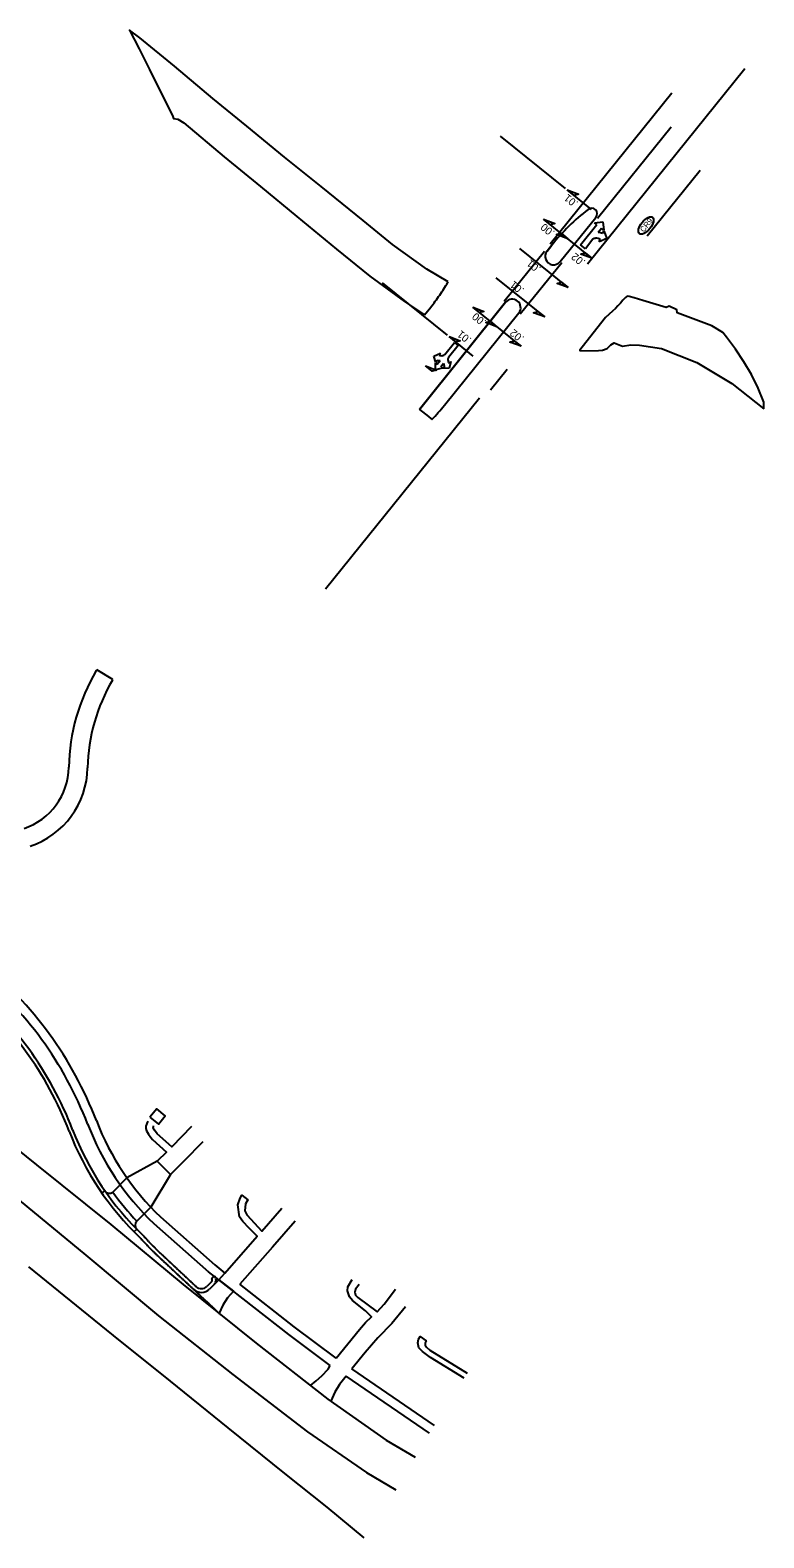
# Model space of a CAD drawing. Extents: x 1487693 to 1489338, y 497936 to 499734.
# Drawn here: x 1488948 to 1489338, y 498934 to 499734 of the extents above; entities that cross this region are included whole.
import ezdxf

# ---------------------------------------------------------------- set-up
doc = ezdxf.new("R2010")
doc.units = 0
for name, color, linetype in [('Default', 7, 'Continuous'), ('Exist Railroads Standard Gauge', 7, 'Continuous'), ('Exist Roads EOP', 7, 'Continuous'), ('Exist Roads EOP Other', 7, 'Continuous'), ('Prop Conc 2ft 6in Curb and Gutter', 7, 'Continuous'), ('Prop Conc 4in Sidewalk', 7, 'Continuous'), ('Prop Conc Driveway', 7, 'Continuous'), ('Prop EOT', 7, 'Continuous'), ('Prop Paved Shoulder', 7, 'Continuous')]:
    doc.layers.add(name, color=color, linetype=linetype)

msp = doc.modelspace()

# ---------------------------------------------------------------- linework, layer by layer
at = {"layer": 'Default'}
for p, q in [((1489244.14, 499610.15), (1489327.8, 499713.89)), ((1489224.38, 499620.7), (1489289.04, 499700.88)), ((1489232.52, 499650.11), (1489197.98, 499677.97)), ((1489288.57, 499682.77), (1489249.4, 499634.2)), ((1489275.86, 499625.03), (1489304, 499659.93)), ((1489246.24, 499639.04), (1489233.4, 499649.4)), ((1489246.53, 499613.12), (1489220.84, 499633.83)), ((1489229.66, 499611.31), (1489248.62, 499634.83)), ((1489229.66, 499611.31), (1489248.62, 499634.83)), ((1489240.45, 499620.27), (1489249.11, 499631.01)), ((1489247.95, 499631.95), (1489252.35, 499632.39)), ((1489249.11, 499631.01), (1489247.95, 499631.95)), ((1489251.68, 499628.94), (1489249.89, 499626.72)), ((1489252.85, 499628), (1489251.68, 499628.94)), ((1489252.35, 499632.39), (1489252.85, 499628)), ((1489247.07, 499623.22), (1489243.02, 499618.2)), ((1489254.43, 499623.51), (1489250.31, 499621.89)), ((1489250.31, 499621.89), (1489250.87, 499623.24)), ((1489252.22, 499626.26), (1489252.82, 499627.64)), ((1489252.82, 499627.64), (1489254.43, 499623.51)), ((1489199.9, 499590.34), (1489221.25, 499616.81)), ((1489233.98, 499597.55), (1489208.29, 499618.27)), ((1489222.65, 499616.96), (1489225.16, 499620.07)), ((1489225.16, 499620.07), (1489222.65, 499616.96)), ((1489243.02, 499618.2), (1489240.45, 499620.27)), ((1489230.44, 499610.68), (1489208.46, 499583.44)), ((1489169.75, 499572.27), (1489135.21, 499600.12)), ((1489221.42, 499581.98), (1489195.73, 499602.7)), ((1489154.86, 499532.89), (1489200.68, 499589.72)), ((1489200.68, 499589.72), (1489154.86, 499532.89)), ((1489168.14, 499535.03), (1489207.69, 499584.07)), ((1489168.14, 499535.03), (1489207.69, 499584.07)), ((1489208.87, 499566.41), (1489183.18, 499587.13)), ((1489168.4, 499561.93), (1489173.59, 499568.33)), ((1489175.46, 499566.81), (1489170.25, 499560.37)), ((1489183.47, 499561.2), (1489170.62, 499571.56)), ((1489173.59, 499568.33), (1489175.46, 499566.81)), ((1489162.61, 499561.16), (1489166, 499562.8)), ((1489163.53, 499557.84), (1489162.61, 499561.16)), ((1489163.45, 499553.83), (1489163.5, 499557.49)), ((1489163.5, 499557.49), (1489164.29, 499556.85)), ((1489164.09, 499559.02), (1489163.53, 499557.84)), ((1489164.29, 499556.85), (1489165.88, 499558.82)), ((1489166, 499562.8), (1489165.44, 499561.62)), ((1489167.73, 499557.26), (1489166.17, 499555.33)), ((1489170.6, 499557.45), (1489171.64, 499558.24)), ((1489171.64, 499558.24), (1489170.7, 499554.6)), ((1489166.95, 499554.69), (1489163.45, 499553.83)), ((1489166.17, 499555.33), (1489166.95, 499554.69)), ((1489167.29, 499554.79), (1489168.33, 499555.58)), ((1489170.7, 499554.6), (1489167.29, 499554.79)), ((1489201.46, 499554.04), (1489192.67, 499543.14)), ((1489105.05, 499437.68), (1489186.71, 499538.94)), ((1489159.62, 499529.05), (1489161.18, 499527.79)), ((1489161.18, 499527.79), (1489161.56, 499527.49))]:
    msp.add_line(p, q, dxfattribs=at)
for points in [[(1489170.07, 499600.67), (1489158.75, 499607.4), (1489140.66, 499620.46), (1489125.03, 499633.21), (1489102.63, 499651.13), (1489083.17, 499666.86), (1489063.28, 499683.21), (1489045.07, 499697.98), (1489024.72, 499715.05), (1489006.27, 499730.11), (1489000.95, 499734.21), (1489005.92, 499724.24)], [(1489005.92, 499724.24), (1489011.46, 499713.24), (1489016.16, 499703.9), (1489023.69, 499688.94)], [(1489023.69, 499688.94), (1489024.3, 499687.23), (1489026.5, 499686.99), (1489029.65, 499684.95), (1489051.14, 499666.9), (1489070.45, 499651.25), (1489089.7, 499635.25), (1489110.82, 499618.01), (1489128.51, 499603.56), (1489146.94, 499590.2), (1489157.49, 499583.15)], [(1489157.49, 499583.15), (1489158.35, 499584.03), (1489160.27, 499586.34), (1489161.54, 499587.88), (1489162.14, 499588.68), (1489162.75, 499589.48), (1489163.32, 499590.3), (1489163.91, 499591.11), (1489164.51, 499591.91), (1489165.09, 499592.73), (1489165.67, 499593.54), (1489166.23, 499594.38), (1489166.77, 499595.22), (1489167.31, 499596.07), (1489167.85, 499596.92), (1489168.98, 499598.58), (1489169.52, 499599.43), (1489170.07, 499600.67)], [(1489266.26, 499592.78), (1489266.26, 499592.78), (1489265.22, 499592.91), (1489264.42, 499592.27), (1489263.71, 499591.56), (1489263.01, 499590.84), (1489261.68, 499589.34), (1489260.34, 499587.85), (1489258.95, 499586.4), (1489257.52, 499584.98), (1489253.73, 499581.62), (1489253.72, 499581.62), (1489241.29, 499565.96), (1489240.14, 499564.33), (1489240.17, 499564.01)], [(1489316.01, 499573.61), (1489310.3, 499577.17), (1489291.78, 499584.19), (1489291.69, 499585.76), (1489287.56, 499587.6), (1489285.94, 499587.02), (1489273.63, 499590.72), (1489269.03, 499592.11), (1489266.26, 499592.78)], [(1489337.85, 499533.16), (1489337.76, 499536.7), (1489334.74, 499544.15), (1489331.25, 499551.32), (1489327.17, 499558.17), (1489322.71, 499564.76), (1489318.01, 499571.17), (1489316.01, 499573.61)], [(1489250, 499564.09), (1489252.14, 499564.24), (1489254.62, 499565.28), (1489255.42, 499566.15), (1489256.62, 499567.2), (1489258.31, 499568.22), (1489262.77, 499566.37), (1489267.18, 499567.1)], [(1489267.18, 499567.1), (1489271.81, 499567.03), (1489283.45, 499565.21), (1489302.26, 499557.74), (1489320.91, 499546.7), (1489337.85, 499533.16)], [(1489240.17, 499564.01), (1489250, 499564.09)], [(1489154.86, 499532.89), (1489154.96, 499532.8), (1489156.52, 499531.55), (1489159.62, 499529.05)]]:
    msp.add_lwpolyline(points, dxfattribs=at)
for points in [[(1489233.4, 499649.4), (1489239.33, 499647.19), (1489237, 499646.5)], [(1489220.84, 499633.83), (1489226.77, 499631.62), (1489224.44, 499630.93)], [(1489233.69, 499623.48), (1489227.76, 499625.69), (1489230.09, 499626.38)], [(1489246.53, 499613.12), (1489240.61, 499615.33), (1489242.93, 499616.02)], [(1489233.98, 499597.55), (1489228.05, 499599.76), (1489230.38, 499600.45)], [(1489183.18, 499587.13), (1489189.11, 499584.92), (1489186.78, 499584.23)], [(1489221.42, 499581.98), (1489215.5, 499584.19), (1489217.82, 499584.89)], [(1489196.02, 499576.77), (1489190.1, 499578.98), (1489192.42, 499579.67)], [(1489170.62, 499571.56), (1489176.55, 499569.35), (1489174.22, 499568.66)], [(1489208.87, 499566.41), (1489202.94, 499568.62), (1489205.27, 499569.32)], [(1489158.07, 499555.99), (1489164, 499553.78), (1489161.67, 499553.09)]]:
    msp.add_lwpolyline(points, close=True, dxfattribs=at)
for centre, radius, start, end in [((1489317.79, 499545.37), 119, 128.05665, 141.11565), ((1489317.79, 499545.37), 119, 128.05665, 141.11565), ((1489246.29, 499636.71), 3, 321.11565, 128.05665), ((1489246.29, 499636.71), 3, 321.11565, 128.05665), ((1489248.57, 499621.19), 2.52, 90.18879, 126.50079), ((1489248.85, 499619.29), 4.43, 62.82532, 93.67888), ((1489250.18, 499622.31), 4.43, 62.70651, 93.58511), ((1489226.15, 499614.14), 4.5, 141.11565, 321.11565), ((1489226.15, 499614.14), 4.5, 141.11565, 321.11565), ((1489204.18, 499586.89), 4.5, 321.11565, 141.11565), ((1489204.18, 499586.89), 4.5, 321.11565, 141.11565), ((1489067.72, 499616.01), 129, 316.66965, 321.11565)]:
    msp.add_arc(centre, radius, start, end, dxfattribs=at)
msp.add_ellipse((1489275.24, 499630.49), major_axis=(3.52, 4.36), ratio=0.462467, dxfattribs=at)
for centre, major_axis, start_param, end_param in [((1489166.07, 499562.46), (-2.52, -3.1), 0.196592, 0.735719), ((1489167.4, 499565.08), (-2.52, -3.1), 0.203036, 0.742869), ((1489167.45, 499563.53), (-1.43, -1.77), 0.681955, 1.288737), ((1489171.27, 499558.24), (-2.52, -3.1), 5.554392, 6.091543), ((1489172.03, 499559.82), (-1.43, -1.77), 5.025308, 5.60123), ((1489173.56, 499560.09), (-2.52, -3.1), 5.540317, 6.085081)]:
    msp.add_ellipse(centre, major_axis=major_axis, ratio=0.8, start_param=start_param, end_param=end_param, dxfattribs=at)
at = {"layer": 'Exist Railroads Standard Gauge'}
msp.add_lwpolyline([(1489125.56, 498933.79), (1489105.79, 498950), (1489083.46, 498967.96), (1489053.28, 498992.22), (1489018.86, 499019.95), (1488995.28, 499038.96), (1488972.75, 499057.15), (1488947.35, 499077.62)], dxfattribs=at)
at = {"layer": 'Exist Roads EOP'}
for points in [[(1488820.51, 499188.47), (1488839.08, 499189.45), (1488852.47, 499187.96), (1488871.27, 499182.3), (1488872.89, 499182.88), (1488877.01, 499181.04), (1488877.11, 499179.47), (1488895.62, 499172.45), (1488918.37, 499158.28), (1488951.48, 499131.73), (1488990.9, 499100.07), (1489029.29, 499068.35), (1489068.11, 499037.11), (1489106.28, 499007.35), (1489137.25, 498985.73), (1489152.63, 498976.62)], [(1488852.51, 499162.38), (1488857.14, 499162.31), (1488868.78, 499160.49), (1488887.58, 499153.02), (1488906.23, 499141.98), (1488939.26, 499115.6), (1488977.74, 499083.85), (1489016.26, 499051.68), (1489055.69, 499020.57), (1489095.36, 498990.11), (1489126.76, 498968.54), (1489142.29, 498959.28)]]:
    msp.add_lwpolyline(points, dxfattribs=at)
at = {"layer": 'Exist Roads EOP Other'}
for p, q in [((1489162.83, 498993.48), (1489118.92, 499023.49)), ((1489160.2, 498989.42), (1489115.9, 499019.67))]:
    msp.add_line(p, q, dxfattribs=at)
msp.add_lwpolyline([(1489011.73, 499157.04), (1489016.2, 499153.4), (1489019.84, 499157.87), (1489015.37, 499161.51)], close=True, dxfattribs=at)
for points in [[(1489010.64, 499155.03), (1489010.03, 499153.76), (1489009.6, 499152.43), (1489009.54, 499151.19), (1489009.91, 499149.95), (1489010.9, 499148.11), (1489012.2, 499146.31), (1489013.14, 499145.21), (1489020.5, 499138.63), (1489015.64, 499133.75)], [(1489033.88, 499152.24), (1489023.35, 499141.34), (1489015.58, 499148.35), (1489014.06, 499150.17), (1489013.47, 499151.42), (1489013.56, 499152.09), (1489013.68, 499152.47)], [(1489022.63, 499126.72), (1489029.99, 499134.03), (1489039.99, 499144.23)], [(1489051.56, 499074.32), (1489068.75, 499093.96), (1489064.42, 499098.24), (1489061.03, 499101.7), (1489059.3, 499104.2), (1489058.33, 499110.63), (1489059.61, 499114.21), (1489060.57, 499115.78), (1489063.69, 499113.31), (1489062.48, 499111.17), (1489062.22, 499107.42), (1489063.14, 499105.32), (1489071.13, 499096.65), (1489081.87, 499108.9)], [(1489088.81, 499101.94), (1489076.82, 499088.19), (1489059.44, 499068.48)], [(1489107.54, 499025.35), (1489085.54, 499041.81), (1489048.37, 499070.79)], [(1489110.68, 499029.19), (1489088.27, 499045.74), (1489059.44, 499068.48)], [(1489110.68, 499029.19), (1489123.04, 499044.47), (1489126.27, 499048.2), (1489129.43, 499051.07), (1489126.21, 499054.36), (1489119.29, 499059.75), (1489117.78, 499061.68), (1489116.73, 499064.85), (1489116.8, 499067.06), (1489119.17, 499070.89)], [(1489122.78, 499068.28), (1489120.9, 499065.79), (1489120.51, 499064.19), (1489120.96, 499062.67), (1489122.15, 499061.31), (1489132.4, 499053.85), (1489136.17, 499057.9), (1489142.24, 499065.86)], [(1489147.5, 499056.46), (1489140.18, 499047.54), (1489132.86, 499040.02), (1489126.03, 499032.2), (1489118.92, 499023.49)], [(1489178.68, 499018.65), (1489160.79, 499029.54), (1489156.59, 499032.64), (1489154.62, 499034.62), (1489153.98, 499037.34), (1489154.46, 499039.28), (1489155.28, 499040.73), (1489158.49, 499038.41), (1489158.01, 499037.27), (1489158, 499036.04), (1489158.62, 499035.01), (1489160.47, 499033.46), (1489180.16, 499021.19)], [(1489097.06, 499014.63), (1489100.07, 499017.16), (1489103.11, 499019.85), (1489106.34, 499023.42), (1489107.54, 499025.35)], [(1489115.9, 499019.67), (1489112.46, 499015.27), (1489109.88, 499011.21), (1489107.86, 499006.36)]]:
    msp.add_lwpolyline(points, dxfattribs=at)
at = {"layer": 'Prop Conc 2ft 6in Curb and Gutter'}
for p, q in [((1489044.52, 499069.81), (1489041.95, 499067.29)), ((1489044.43, 499071.32), (1489045.65, 499072.9))]:
    msp.add_line(p, q, dxfattribs=at)
for centre, radius, start, end in [((1488796.55, 499083.6), 186.5, 21.00993, 51.11565), ((1489113.94, 499205.5), 153.5, 201.00993, 226.34297), ((1489043.82, 499070.53), 1, 314.53001, 52.25672), ((1489039.05, 499070.24), 4.14, 226.91206, 314.53)]:
    msp.add_arc(centre, radius, start, end, dxfattribs=at)
msp.add_spline([(1489007.98, 499094.44), (1489008.47, 499093.9), (1489008.96, 499093.35), (1489009.46, 499092.81), (1489009.96, 499092.27), (1489010.46, 499091.73), (1489010.97, 499091.2), (1489011.47, 499090.67), (1489011.99, 499090.14), (1489012.5, 499089.61), (1489013.01, 499089.08), (1489013.53, 499088.56), (1489014.06, 499088.04), (1489014.58, 499087.52), (1489015.11, 499087), (1489015.64, 499086.49), (1489016.17, 499085.98), (1489016.71, 499085.46), (1489017.3, 499084.91), (1489017.9, 499084.35), (1489018.49, 499083.8), (1489019.08, 499083.24), (1489019.68, 499082.69), (1489020.27, 499082.13), (1489020.86, 499081.57), (1489021.46, 499081.02), (1489022.05, 499080.46), (1489022.64, 499079.91), (1489023.24, 499079.35), (1489023.83, 499078.8), (1489024.43, 499078.24), (1489025.02, 499077.69), (1489025.61, 499077.13), (1489026.21, 499076.58), (1489026.8, 499076.02), (1489027.39, 499075.47), (1489027.99, 499074.91), (1489028.58, 499074.36), (1489029.17, 499073.8), (1489029.77, 499073.25), (1489030.36, 499072.69), (1489030.96, 499072.14), (1489031.55, 499071.58), (1489032.14, 499071.02), (1489032.74, 499070.47), (1489033.33, 499069.91), (1489033.92, 499069.36), (1489034.52, 499068.8), (1489035.11, 499068.25), (1489035.7, 499067.69), (1489036.22, 499067.21)], degree=3, dxfattribs=at)
at = {"layer": 'Prop Conc 4in Sidewalk'}
for p, q in [((1488983.22, 499394.23), (1488983.44, 499394.61)), ((1488992.05, 499389.52), (1488983.44, 499394.61)), ((1488991.83, 499389.14), (1488992.05, 499389.52)), ((1489013.84, 499100.59), (1489042.81, 499075.1)), ((1489017.3, 499104.21), (1489046.26, 499078.72)), ((1489046.26, 499078.72), (1489051.56, 499074.32)), ((1489048.37, 499070.79), (1489042.81, 499075.1)), ((1489048.37, 499070.79), (1489051.56, 499074.32))]:
    msp.add_line(p, q, dxfattribs=at)
for centre, radius, start, end in [((1489073.61, 499340.81), 105, 149.4145, 178.88465), ((1489073.61, 499340.81), 95, 149.4145, 178.88465), ((1488933.64, 499343.53), 35, 288.72221, 358.88465), ((1488933.64, 499343.53), 45, 288.72221, 358.88465), ((1488796.55, 499083.6), 200, 21.00993, 51.11565), ((1488796.55, 499083.6), 195, 21.00993, 51.11565), ((1489113.94, 499205.5), 145, 201.00993, 226.34297), ((1489113.94, 499205.5), 140, 201.00993, 226.34297)]:
    msp.add_arc(centre, radius, start, end, dxfattribs=at)
at = {"layer": 'Prop Conc Driveway'}
for p, q in [((1489015.64, 499133.75), (1488999.51, 499124.84)), ((1489022.63, 499126.72), (1489015.64, 499133.75)), ((1488999.51, 499124.84), (1488991.97, 499117.34)), ((1489022.63, 499126.72), (1489012.24, 499109.29)), ((1488986.16, 499116.84), (1488987.78, 499118.01)), ((1489012.24, 499109.29), (1489004.79, 499101.89)), ((1489003.23, 499096.27), (1489004.68, 499097.64))]:
    msp.add_line(p, q, dxfattribs=at)
for centre, radius, start, end in [((1488990.21, 499119.77), 3, 215.94114, 305.8734), ((1489113.34, 499204.99), 149.71, 215.83468, 223.52528), ((1489006.85, 499099.71), 3, 133.49719, 223.47069)]:
    msp.add_arc(centre, radius, start, end, dxfattribs=at)
at = {"layer": 'Prop EOT'}
for p, q in [((1489048.37, 499070.79), (1489043.36, 499065.86)), ((1489048.37, 499070.79), (1489056.05, 499064.71)), ((1489052.88, 499061.14), (1489050.53, 499057.32)), ((1489056.05, 499064.71), (1489052.88, 499061.14)), ((1489050.53, 499057.32), (1489048.41, 499053.08))]:
    msp.add_line(p, q, dxfattribs=at)
for centre, radius, start, end in [((1488796.55, 499083.6), 184.5, 21.00993, 51.11565), ((1489113.94, 499205.5), 155.5, 201.00993, 226.34297), ((1489039.05, 499070.24), 6.14, 226.91206, 314.53)]:
    msp.add_arc(centre, radius, start, end, dxfattribs=at)
msp.add_spline([(1489006.6, 499093), (1489007.09, 499092.44), (1489007.59, 499091.89), (1489008.1, 499091.34), (1489008.61, 499090.8), (1489009.12, 499090.26), (1489009.63, 499089.71), (1489010.14, 499089.17), (1489010.66, 499088.64), (1489011.18, 499088.1), (1489011.7, 499087.57), (1489012.23, 499087.04), (1489012.76, 499086.51), (1489013.29, 499085.99), (1489013.83, 499085.47), (1489014.36, 499084.95), (1489014.9, 499084.43), (1489015.45, 499083.91), (1489016.04, 499083.35), (1489016.64, 499082.8), (1489017.23, 499082.24), (1489017.82, 499081.69), (1489018.42, 499081.13), (1489019.01, 499080.58), (1489019.6, 499080.02), (1489020.2, 499079.47), (1489020.79, 499078.91), (1489021.38, 499078.36), (1489021.98, 499077.8), (1489022.57, 499077.24), (1489023.17, 499076.69), (1489023.76, 499076.13), (1489024.35, 499075.58), (1489024.95, 499075.02), (1489025.54, 499074.47), (1489026.13, 499073.91), (1489026.73, 499073.36), (1489027.32, 499072.8), (1489027.91, 499072.25), (1489028.51, 499071.69), (1489029.1, 499071.14), (1489029.7, 499070.58), (1489030.29, 499070.03), (1489030.88, 499069.47), (1489031.48, 499068.92), (1489032.07, 499068.36), (1489032.66, 499067.81), (1489033.26, 499067.25), (1489033.85, 499066.69), (1489034.44, 499066.14), (1489035.04, 499065.58), (1489035.63, 499065.03), (1489036.23, 499064.47), (1489036.82, 499063.92), (1489037.41, 499063.36), (1489038.01, 499062.81), (1489038.6, 499062.25), (1489039.19, 499061.7), (1489039.79, 499061.14), (1489040.38, 499060.59), (1489040.97, 499060.03), (1489041.57, 499059.48), (1489042.16, 499058.92), (1489042.76, 499058.37), (1489043.35, 499057.81), (1489043.94, 499057.26), (1489044.54, 499056.7), (1489045.13, 499056.14), (1489045.72, 499055.59), (1489046.32, 499055.03), (1489046.91, 499054.48), (1489047.5, 499053.92), (1489048.1, 499053.37), (1489049.29, 499052.26)], degree=3, dxfattribs=at)
at = {"layer": 'Prop Paved Shoulder'}
msp.add_arc((1489043.82, 499070.53), 3, 314.53001, 52.25672, dxfattribs=at)

# ---------------------------------------------------------------- texts
at = {"layer": 'Default'}
for s, height, rotation, p in [('.01', 4, 141.17553, (1489239.52, 499642.8)), ('.00', 4, 141.17553, (1489227.11, 499627.27)), ('CR9', 3, 51.11565, (1489274.07, 499626.68)), ('.01', 4, 141.17553, (1489219.7, 499608.05)), ('.02', 4, 141.17553, (1489243.39, 499611.6)), ('.01', 4, 141.17553, (1489210.82, 499596.73)), ('.00', 4, 141.17553, (1489190.69, 499579.83)), ('.01', 4, 141.17553, (1489182.8, 499570.42)), ('.02', 4, 141.17553, (1489210.76, 499571.14))]:
    msp.add_text(s, height=height, rotation=rotation, dxfattribs=at).set_placement(p)

doc.saveas('drawing.dxf')
